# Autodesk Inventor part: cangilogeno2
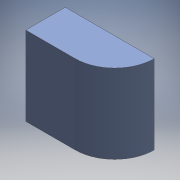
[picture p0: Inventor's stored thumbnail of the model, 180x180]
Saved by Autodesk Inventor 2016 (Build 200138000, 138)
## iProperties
Created: 2016-06
Part Number: cangilogeno2
Material: Genérico
Document SubType Name: Modeling
Designer: adm
Density: 1 g/cm^3
Appearance: Valor por defecto
Author: adm
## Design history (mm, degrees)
sketch "Boceto1"
  geometry: L1 (427.5, 190)-(-22.5, 190); L2 (-22.5, 190)-(-22.5, -10); L3 (-22.5, -10)-(227.5, -10); L4 (427.5, 190)-(427.5, 190); A1 r 200 centre (227.5, 190) between (227.5, -10) and (427.5, 190); 1 further point
  constraints: 8 end point, 2 parallel, 2 point on circle, 2 tangent, 1 centre point, 1 horizontal, 1 perpendicular
  dimensions: "d1" = 200 distance of L2.end L1.end; "d2" = 200 radius of A1; "d6" = 450 distance of L1.start L1.end
extrude "Extrusión1" new body sketch "Boceto1" distance "d3" = 400; taper "d4" = 0 deg
feature "Vaciado1" dims "d5" = 10
node "Sólido1"
